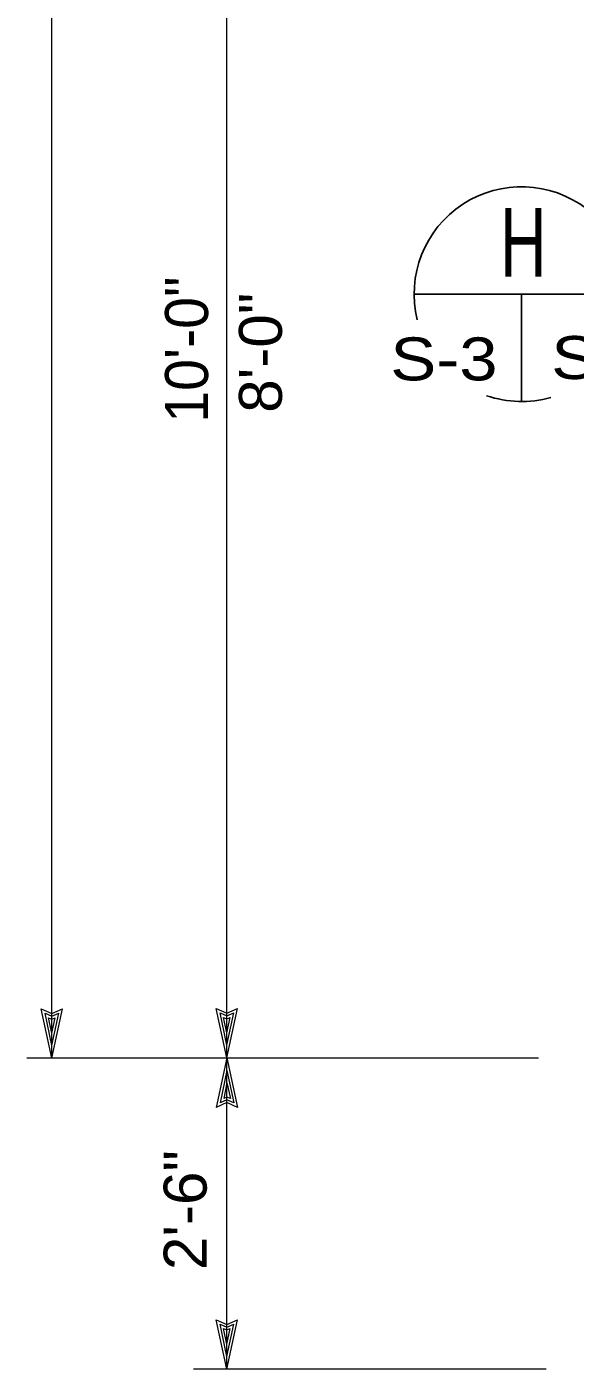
# Model space of a CAD drawing. Extents: x -28.1 to 13.9, y -16.1 to 13.9.
# Drawn here: x -17.946 to -16.351, y 2.489 to 6.396 of the extents above; entities that cross this region are included whole.
import ezdxf
from ezdxf.enums import TextEntityAlignment as Align

# ---------------------------------------------------------------- set-up
doc = ezdxf.new("R2010")
doc.units = 0
doc.header["$LTSCALE"] = 0.05
doc.layers.add('1', color=7, linetype='Continuous', lineweight=13)
doc.layers.add('2', color=7, linetype='Continuous', lineweight=13)

msp = doc.modelspace()

# ---------------------------------------------------------------- linework, layer by layer
at = {"layer": '1'}
for p, q in [((-17.87304, 3.39369), (-17.87304, 10.01569)), ((-17.87304, 3.39369), (-17.90404, 3.53769)), ((-17.87304, 3.43069), (-17.89304, 3.52469)), ((-17.89304, 3.52469), (-17.87304, 3.51569)), ((-17.87304, 3.39369), (-17.84204, 3.53769)), ((-17.87304, 3.43069), (-17.85304, 3.52469)), ((-17.87304, 3.51569), (-17.85304, 3.52469)), ((-17.36404, 3.39469), (-17.39504, 3.53869)), ((-17.36404, 3.43169), (-17.38404, 3.52569)), ((-17.38404, 3.52569), (-17.36404, 3.51669)), ((-17.36404, 3.39469), (-17.33304, 3.53869)), ((-17.36404, 3.43169), (-17.34404, 3.52569)), ((-17.36404, 3.51669), (-17.34404, 3.52569)), ((-17.87304, 3.46669), (-17.88304, 3.51169)), ((-17.88304, 3.51169), (-17.87304, 3.50769)), ((-17.87304, 3.46669), (-17.86404, 3.51169)), ((-17.87304, 3.50769), (-17.86404, 3.51169)), ((-17.36404, 3.46769), (-17.37404, 3.51269)), ((-17.37404, 3.51269), (-17.36404, 3.50869)), ((-17.36404, 3.46769), (-17.35504, 3.51269)), ((-17.36404, 3.50869), (-17.35504, 3.51269)), ((-16.45804, 3.39369), (-17.94604, 3.39369)), ((-17.36404, 3.39469), (-17.39504, 3.25069)), ((-17.36404, 2.48869), (-17.36404, 3.39469)), ((-17.36404, 3.39469), (-17.33304, 3.25069)), ((-17.36404, 3.35769), (-17.38404, 3.26369)), ((-17.36404, 3.32169), (-17.37304, 3.27669)), ((-17.36404, 3.35769), (-17.34404, 3.26369)), ((-17.36404, 3.32169), (-17.35404, 3.27669)), ((-17.36404, 3.27269), (-17.38404, 3.26369)), ((-17.36404, 3.28069), (-17.37304, 3.27669)), ((-17.35404, 3.27669), (-17.36404, 3.28069)), ((-17.34404, 3.26369), (-17.36404, 3.27269)), ((-17.36404, 2.48869), (-17.39504, 2.63269)), ((-17.36404, 2.52569), (-17.38404, 2.61969)), ((-17.38404, 2.61969), (-17.36404, 2.61069)), ((-17.36404, 2.48869), (-17.33304, 2.63269)), ((-17.36404, 2.52569), (-17.34404, 2.61969)), ((-17.36404, 2.61069), (-17.34404, 2.61969)), ((-17.36404, 2.56169), (-17.37404, 2.60669)), ((-17.37404, 2.60669), (-17.36404, 2.60269)), ((-17.36404, 2.56169), (-17.35504, 2.60669)), ((-17.36404, 2.60269), (-17.35504, 2.60669)), ((-16.43504, 2.48869), (-17.46104, 2.48869))]:
    msp.add_line(p, q, dxfattribs=at)
for points in [[(-17.36404, 3.39469), (-17.36404, 7.17869), (-17.36404, 7.56269), (-17.36404, 10.01769)], [(-17.90404, 3.53769), (-17.87304, 3.52369), (-17.84204, 3.53769)], [(-17.39504, 3.53869), (-17.36404, 3.52469), (-17.33304, 3.53869)], [(-17.33304, 3.25069), (-17.36404, 3.26469), (-17.39504, 3.25069)], [(-17.39504, 2.63269), (-17.36404, 2.61869), (-17.33304, 2.63269)]]:
    msp.add_lwpolyline(points, dxfattribs=at)
at = {"layer": '2', "lineweight": 25}
for p, q in [((-16.81904, 5.61769), (-16.19504, 5.61769)), ((-16.50704, 5.61769), (-16.50704, 5.30569))]:
    msp.add_line(p, q, dxfattribs=at)
for start, end in [(341.96976, 193.81208), (251.04049, 285.74671)]:
    msp.add_arc((-16.50704, 5.61769), 0.3125, start, end, dxfattribs=at)

# ---------------------------------------------------------------- texts
at = {"layer": '1'}
msp.add_text('10\'-0"', height=0.125, rotation=90, dxfattribs=at).set_placement((-17.41904, 5.45598), align=Align.CENTER)
at = {"layer": '1', "width": 1.05}
for s, p in [('8\'-0"', (-17.20404, 5.44704)), ('2\'-6"', (-17.42304, 2.95157))]:
    msp.add_text(s, height=0.125, rotation=90, dxfattribs=at).set_placement(p, align=Align.CENTER)
at = {"layer": '2'}
for s, height, width, p in [('H', 0.2, 0.7, (-16.5019, 5.66869)), ('S-3', 0.125, 1.2, (-16.73268, 5.36669)), ('S-3', 0.125, 1.2, (-16.26468, 5.37069))]:
    msp.add_text(s, height=height, dxfattribs=dict(at, width=width)).set_placement(p, align=Align.CENTER)

doc.saveas('drawing.dxf')
